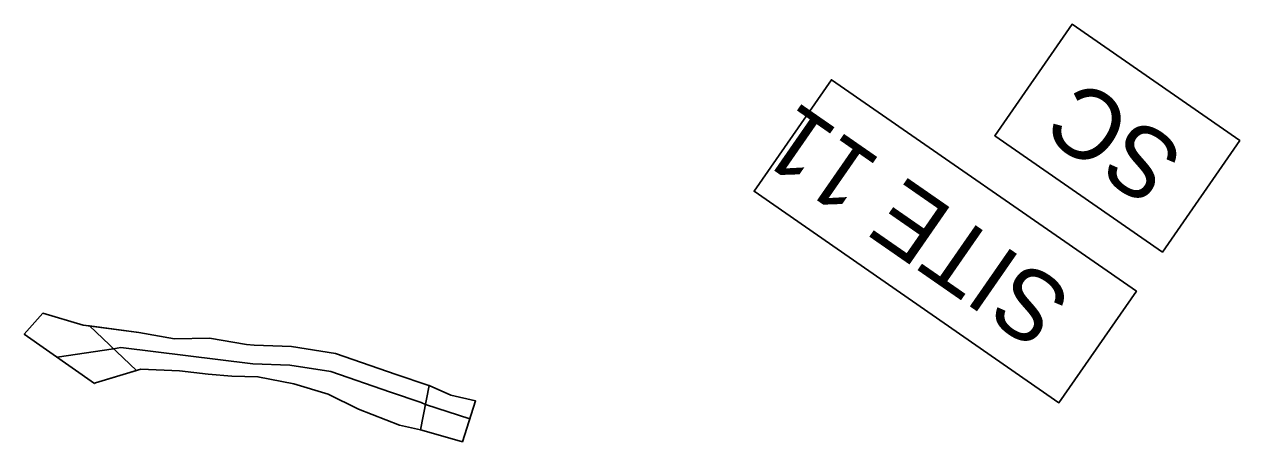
# Model space of a CAD drawing. Extents: x 474218 to 481634, y 484357 to 504997.
# Drawn here: x 479051.3 to 479311.9, y 493981 to 494070.5 of the extents above; entities that cross this region are included whole.
import ezdxf

# ---------------------------------------------------------------- set-up
doc = ezdxf.new("R2010")
doc.units = 0
for name, color, linetype in [('Exist Hydro Jurisdictional Stream or Body of Water', 7, 'Continuous'), ('Old_Level_29', 7, 'Continuous'), ('Prop Earthen Structure Impacts In Surface Waters Hatching CELL', 7, 'Continuous'), ('Prop Grid Mask', 7, 'Continuous'), ('Scratch_Level_4', 7, 'Continuous'), ('Temp Earthen Structure Impacts In Surface Waters Hatching CELL', 7, 'Continuous')]:
    doc.layers.add(name, color=color, linetype=linetype)

msp = doc.modelspace()

# ---------------------------------------------------------------- linework, layer by layer
at = {"layer": 'Exist Hydro Jurisdictional Stream or Body of Water'}
msp.add_lwpolyline([(479295.32, 494021.65), (479259.39, 494046.57), (479275.96, 494070.47), (479311.89, 494045.54)], close=True, dxfattribs=at)
at = {"layer": 'Old_Level_29'}
msp.add_lwpolyline([(479273.15, 493989.33), (479207.78, 494034.68), (479224.36, 494058.59), (479289.74, 494013.24)], close=True, dxfattribs=at)
at = {"layer": 'Prop Earthen Structure Impacts In Surface Waters Hatching CELL'}
for p, q in [((479051.3, 494004.07), (479066.36, 493993.44)), ((479138.12, 493993), (479138.12, 493993)), ((479138.12, 493993), (479138.12, 493993))]:
    msp.add_line(p, q, dxfattribs=at)
for points in [[(479098.92, 494001.84), (479091, 494003.18), (479083.51, 494003.03), (479075.87, 494004.37), (479063.93, 494005.99), (479055.28, 494008.53), (479051.3, 494004.07)], [(479138.12, 493993), (479138.12, 493993), (479138.12, 493993), (479138.12, 493993), (479138.12, 493993), (479137.85, 493993.12), (479131.06, 493995.36), (479118, 493999.91), (479108.6, 494001.39), (479100.59, 494001.66), (479098.92, 494001.84)], [(479066.36, 493993.44), (479066.55, 493993.58), (479076.25, 493996.51), (479084.54, 493996.21), (479090.71, 493995.44), (479095.81, 493995.02)], [(479095.81, 493995.02), (479101.4, 493994.9), (479109.06, 493993.42), (479116.44, 493991.17), (479122.95, 493987.99), (479131.73, 493984.52), (479136.23, 493983.56), (479138.12, 493993), (479138.12, 493993), (479138.12, 493993), (479138.12, 493993), (479138.12, 493993)]]:
    msp.add_lwpolyline(points, dxfattribs=at)
at = {"layer": 'Prop Grid Mask'}
for points in [[(479311.89, 494045.54), (479275.96, 494070.47), (479259.39, 494046.57), (479295.32, 494021.65)], [(479289.74, 494013.24), (479224.36, 494058.59), (479207.78, 494034.68), (479273.15, 493989.33)]]:
    msp.add_lwpolyline(points, close=True, dxfattribs=at)
at = {"layer": 'Scratch_Level_4'}
for p, q in [((479065.31, 494005.8), (479075.32, 493996.23)), ((479136.23, 493983.56), (479138.12, 493993)), ((479137.32, 493988.99), (479146.83, 493985.9))]:
    msp.add_line(p, q, dxfattribs=at)
msp.add_lwpolyline([(479066.36, 493993.44), (479051.3, 494004.07), (479055.28, 494008.53), (479063.93, 494005.99), (479065.31, 494005.8), (479075.32, 493996.23), (479066.55, 493993.58)], close=True, dxfattribs=at)
for points in [[(479098.92, 494001.84), (479091, 494003.18), (479083.51, 494003.03), (479075.87, 494004.37), (479065.31, 494005.8)], [(479070.4, 494000.92), (479058.31, 493999.12)], [(479137.32, 493988.99), (479136.42, 493989.38), (479129.78, 493991.57), (479117.02, 493996.01), (479108.22, 493997.4), (479100.31, 493997.67), (479072.01, 494001.16), (479070.4, 494000.92)], [(479138.12, 493993), (479137.85, 493993.12), (479131.06, 493995.36), (479118, 493999.91), (479108.6, 494001.39), (479100.59, 494001.66), (479098.92, 494001.84)], [(479075.32, 493996.23), (479076.25, 493996.51), (479084.54, 493996.21), (479090.71, 493995.44), (479095.81, 493995.02)], [(479095.81, 493995.02), (479101.4, 493994.9), (479109.06, 493993.42), (479116.44, 493991.17), (479122.95, 493987.99), (479131.73, 493984.52), (479136.23, 493983.56), (479138.12, 493993)]]:
    msp.add_lwpolyline(points, dxfattribs=at)
at = {"layer": 'Temp Earthen Structure Impacts In Surface Waters Hatching CELL'}
msp.add_line((479138.12, 493993), (479136.23, 493983.56), dxfattribs=at)
msp.add_lwpolyline([(479136.23, 493983.56), (479145.06, 493981.06), (479145.06, 493981.06), (479145.06, 493981.06), (479145.06, 493981.06), (479145.25, 493980.98), (479148.06, 493989.72), (479148.06, 493989.72), (479142.72, 493990.99), (479138.12, 493993)], dxfattribs=at)

# ---------------------------------------------------------------- texts
at = {"layer": 'Exist Hydro Jurisdictional Stream or Body of Water'}
msp.add_text('SC', height=15, rotation=145.252, dxfattribs=at).set_placement((479300.71, 494043.25))
at = {"layer": 'Old_Level_29'}
msp.add_text('SITE 11', height=15, rotation=145.252, dxfattribs=at).set_placement((479276.63, 494012.58))

doc.saveas('drawing.dxf')
